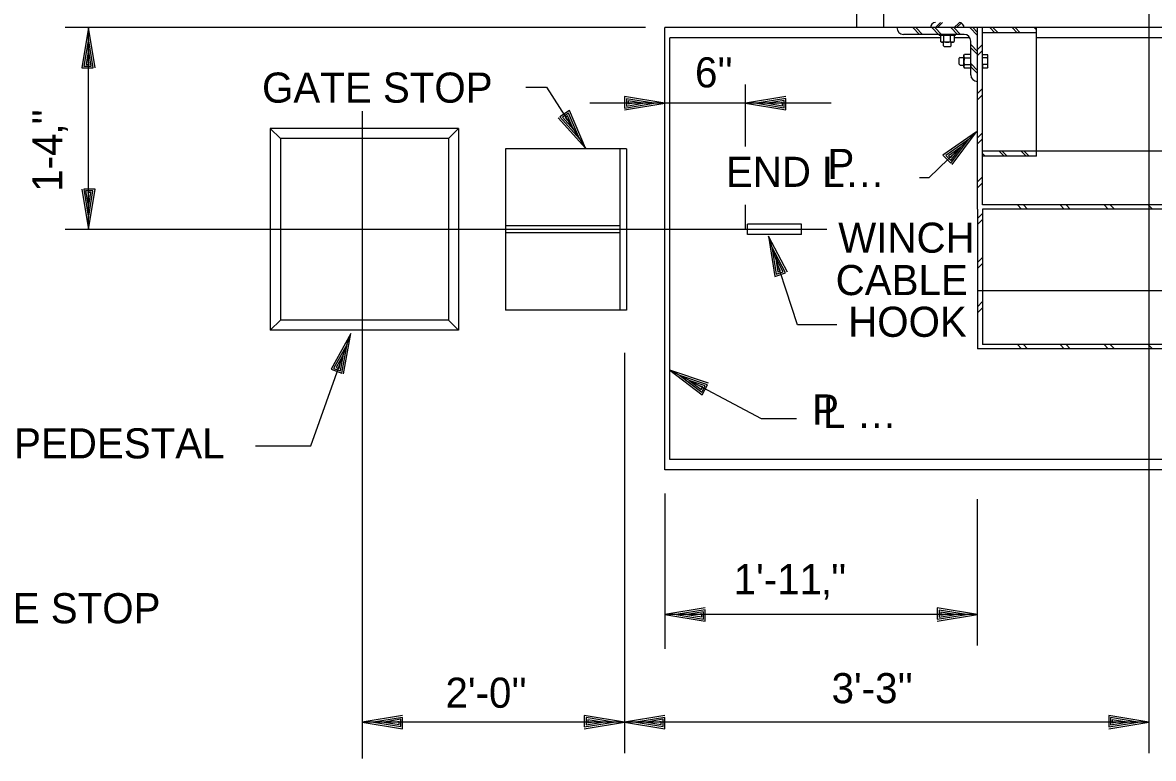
# Model space of a CAD drawing. Extents: x 0 to 53.3, y -2.9 to 37.3.
# Drawn here: x 7.1 to 14.11, y 12.87 to 17.43 of the extents above; entities that cross this region are included whole.
import ezdxf

# ---------------------------------------------------------------- set-up
doc = ezdxf.new("R2010")
doc.units = 0
for name, color, linetype in [('Level 2', 7, 'Continuous'), ('Level 3', 7, 'Continuous'), ('Level 44', 7, 'Continuous'), ('Level 50', 7, 'Continuous')]:
    doc.layers.add(name, color=color, linetype=linetype)

msp = doc.modelspace()

# ---------------------------------------------------------------- linework, layer by layer
at = {"layer": 'Level 2'}
for p, q in [((12.2655, 17.5489), (12.2655, 17.4006)), ((12.4322, 17.5489), (12.4322, 17.4006)), ((47.1285, 17.4006), (11.078, 17.4006)), ((11.078, 14.661), (11.078, 17.4006)), ((13.0155, 16.2756), (13.0155, 17.4006)), ((13.0468, 16.3016), (13.0468, 17.4006)), ((13.3801, 17.3693), (13.3801, 17.4006)), ((13.3801, 16.6037), (13.3801, 17.4006)), ((12.7862, 17.3381), (11.1093, 17.3381)), ((11.1093, 14.7235), (11.1093, 17.3381)), ((12.9322, 17.3589), (12.5572, 17.3589)), ((12.7787, 17.3589), (12.7787, 17.3514)), ((12.8774, 17.3514), (12.7787, 17.3514)), ((12.7862, 17.3514), (12.7862, 17.314)), ((12.7918, 17.3107), (12.7862, 17.314)), ((12.8643, 17.3107), (12.7918, 17.3107)), ((12.8038, 17.2873), (12.8038, 17.3107)), ((12.807, 17.3139), (12.807, 17.3514)), ((12.849, 17.3139), (12.849, 17.3514)), ((12.8523, 17.2873), (12.8523, 17.3107)), ((12.8643, 17.3107), (12.8699, 17.314)), ((12.8699, 17.3514), (12.8699, 17.314)), ((12.9683, 17.3381), (12.8699, 17.3381)), ((12.8774, 17.3589), (12.8774, 17.3514)), ((12.9738, 17.1089), (12.9738, 17.3173)), ((13.3801, 17.3693), (13.0468, 17.3693)), ((47.1285, 17.3381), (13.3801, 17.3381)), ((12.8038, 17.2873), (12.8098, 17.2812)), ((12.8462, 17.2812), (12.8098, 17.2812)), ((12.8523, 17.2873), (12.8462, 17.2812)), ((12.9074, 17.2165), (12.9013, 17.2105)), ((12.9013, 17.1741), (12.9013, 17.2105)), ((12.9074, 17.168), (12.9013, 17.1741)), ((12.9074, 17.2165), (12.9308, 17.2165)), ((12.9308, 17.2285), (12.9341, 17.2341)), ((12.9308, 17.156), (12.9308, 17.2285)), ((12.934, 17.2132), (12.9738, 17.2132)), ((12.934, 17.1713), (12.9738, 17.1713)), ((12.9738, 17.2341), (12.9341, 17.2341)), ((12.9738, 17.1504), (12.9738, 17.2341)), ((12.9738, 17.1716), (12.9738, 17.1504)), ((13.0442, 17.2168), (13.0457, 17.2168)), ((13.0442, 17.1683), (13.0457, 17.1683)), ((13.0457, 17.1506), (13.0457, 17.2344)), ((13.0457, 17.2344), (13.0764, 17.2344)), ((13.0765, 17.2135), (13.0457, 17.2135)), ((13.0457, 17.1718), (13.0457, 17.1506)), ((13.0765, 17.1715), (13.0457, 17.1715)), ((13.0797, 17.2288), (13.0764, 17.2344)), ((13.0797, 17.1563), (13.0797, 17.2288)), ((12.9074, 17.168), (12.9308, 17.168)), ((12.9308, 17.156), (12.9341, 17.1504)), ((12.9738, 17.1504), (12.9341, 17.1504)), ((13.0457, 17.1506), (13.0764, 17.1506)), ((13.0797, 17.1563), (13.0764, 17.1506)), ((9.7993, 16.7756), (8.6326, 16.7756)), ((9.7368, 16.7131), (8.6951, 16.7131)), ((10.841, 16.6506), (10.091, 16.6506)), ((13.3801, 16.635), (13.0468, 16.635)), ((15.1874, 16.635), (13.3801, 16.635)), ((13.3801, 16.6037), (13.0468, 16.6037)), ((47.1285, 16.3016), (13.0468, 16.3016)), ((47.1285, 16.2756), (13.0468, 16.2756)), ((12.0815, 16.1506), (7.3607, 16.1506)), ((10.7993, 16.1714), (10.091, 16.1714)), ((10.7993, 16.1298), (10.091, 16.1298)), ((11.591, 16.1193), (11.591, 16.1818)), ((11.9243, 16.1818), (11.591, 16.1818)), ((11.9243, 16.1193), (11.591, 16.1193)), ((11.9243, 16.1193), (11.9243, 16.1818)), ((47.1285, 15.7698), (13.0155, 15.7698)), ((10.841, 15.6506), (10.091, 15.6506)), ((9.7368, 15.5881), (8.6951, 15.5881)), ((9.7993, 15.5256), (8.6326, 15.5256)), ((47.1285, 15.4364), (13.0468, 15.4364)), ((47.1285, 15.4104), (13.0155, 15.4104)), ((47.1285, 14.7235), (11.1093, 14.7235)), ((47.1285, 14.661), (11.078, 14.661)), ((13.0155, 13.572), (13.0155, 14.4783))]:
    msp.add_line(p, q, dxfattribs=at)
for centre, radius, start, end in [((12.5572, 17.4006), 0.0417, 180, 270), ((12.7551, 17.4006), 0.0313, 90, 180), ((12.9009, 17.4006), 0.0313, 0, 90), ((12.7968, 17.3288), 0.0182, 239.71241, 304.51098), ((12.8283, 17.3834), 0.0727, 253.01837, 286.49659), ((12.8593, 17.3288), 0.0182, 235.48902, 300.28759), ((12.9322, 17.3172), 0.0417, 0, 90), ((12.949, 17.2235), 0.0182, 149.71241, 214.51098), ((12.949, 17.161), 0.0182, 145.48902, 210.28759), ((13.0036, 17.192), 0.0727, 163.01837, 196.49659), ((13.0615, 17.2237), 0.0182, 325.48902, 30.28759), ((13.007, 17.1922), 0.0727, 343.50341, 16.98163), ((13.0615, 17.1612), 0.0182, 329.71241, 34.51098), ((13.0155, 17.1089), 0.0417, 180, 270)]:
    msp.add_arc(centre, radius, start, end, dxfattribs=at)
at = {"layer": 'Level 3'}
for p, q in [((9.203, 16.8825), (9.203, 12.8719)), ((8.6326, 16.7756), (8.6326, 15.5256)), ((9.7993, 16.7756), (9.7993, 15.5256)), ((13.0096, 16.7546), (13.0096, 16.7546)), ((8.6951, 16.7131), (8.6951, 15.5881)), ((9.7368, 16.7131), (9.7368, 15.5881)), ((10.5483, 16.7125), (10.5483, 16.7125)), ((12.9597, 16.7065), (12.9597, 16.7065)), ((10.091, 16.6506), (10.091, 15.6506)), ((10.5856, 16.6541), (10.5856, 16.6541)), ((10.7993, 16.6506), (10.7993, 15.6506)), ((10.841, 16.6506), (10.841, 15.6506)), ((11.7201, 16.1088), (11.7201, 16.1088)), ((11.7418, 16.0429), (11.7418, 16.0429)), ((9.1314, 15.5044), (9.1314, 15.5044)), ((9.1082, 15.4391), (9.1082, 15.4391)), ((11.1093, 15.2783), (11.1093, 15.2783)), ((11.1704, 15.2457), (11.1704, 15.2457))]:
    msp.add_line(p, q, dxfattribs=at)
for points in [[(12.6556, 17.3589), (12.614, 17.4006)], [(12.6745, 17.3589), (12.6328, 17.4006)], [(12.7735, 17.3589), (12.7318, 17.4006)], [(12.7923, 17.3589), (12.7507, 17.4006)], [(12.755, 17.4011), (12.7862, 17.4324)], [(12.7671, 17.4006), (12.7984, 17.4318)], [(12.8913, 17.3589), (12.8497, 17.4006)], [(12.9102, 17.3589), (12.8685, 17.4006)], [(12.8717, 17.4006), (12.9025, 17.4313)], [(12.885, 17.4006), (12.9135, 17.4292)], [(13.0155, 17.3526), (12.9675, 17.4006)], [(13.0155, 17.3715), (12.9864, 17.4006)], [(13.0155, 17.2536), (12.9738, 17.2953)], [(13.0155, 17.2348), (12.9738, 17.2764)], [(13.0155, 17.1358), (12.9738, 17.1774)], [(13.0155, 17.1169), (12.9738, 17.1585)], [(10.2156, 17.0308), (10.3454, 17.0308), (10.5856, 16.6541)], [(10.4167, 16.8421), (10.5856, 16.6541), (10.4864, 16.8865), (10.4268, 16.8485), (10.5483, 16.7125), (10.4809, 16.8703), (10.4427, 16.846), (10.5125, 16.7687), (10.4754, 16.8542), (10.4597, 16.8441), (10.4752, 16.8272)], [(12.6557, 16.4714), (12.7164, 16.4714), (13.0096, 16.7546)], [(12.859, 16.5517), (13.0096, 16.7546), (12.8015, 16.6111), (12.8506, 16.5603), (12.9597, 16.7065), (12.8185, 16.609), (12.85, 16.5764), (12.9118, 16.6602), (12.8354, 16.6068), (12.8484, 16.5934), (12.8619, 16.612)], [(12.143, 15.5588), (11.9008, 15.5588), (11.7201, 16.1088)], [(11.8372, 15.8848), (11.7201, 16.1088), (11.7587, 15.859), (11.8258, 15.8811), (11.7418, 16.0429), (11.768, 15.8733), (11.8111, 15.8874), (11.7626, 15.9796), (11.7774, 15.8876), (11.7951, 15.8934), (11.7842, 15.9137)], [(8.5406, 14.8094), (8.8847, 14.8094), (9.1314, 15.5044)], [(9.0869, 15.2556), (9.1314, 15.5044), (9.0091, 15.2833), (9.0756, 15.2596), (9.1082, 15.4391), (9.0252, 15.2889), (9.0679, 15.2737), (9.0859, 15.3763), (9.0413, 15.2945), (9.0589, 15.2882), (9.0627, 15.3109)], [(11.8935, 14.9757), (11.6773, 14.9757), (11.1093, 15.2783)], [(11.3488, 15.1975), (11.1093, 15.2783), (11.3099, 15.1246), (11.3431, 15.1869), (11.1704, 15.2457), (11.3068, 15.1414), (11.3281, 15.1814), (11.2293, 15.2143), (11.3036, 15.1581), (11.3124, 15.1746), (11.2905, 15.1817)]]:
    msp.add_lwpolyline(points, dxfattribs=at)
at = {"layer": 'Level 44'}
for p, q in [((13.1237, 17.3693), (13.0925, 17.4006)), ((13.1426, 17.3693), (13.1113, 17.4006)), ((13.2604, 17.3693), (13.2292, 17.4006)), ((13.2793, 17.3693), (13.248, 17.4006)), ((13.3801, 17.3864), (13.3659, 17.4006)), ((13.0155, 17.2649), (13.0468, 17.2961)), ((13.0155, 17.2272), (13.0468, 17.2584)), ((11.578, 16.6636), (11.578, 17.048)), ((13.0155, 16.9915), (13.0468, 17.0227)), ((13.0155, 16.9538), (13.0468, 16.985)), ((11.078, 16.9317), (10.6135, 16.9317)), ((11.578, 16.9317), (11.078, 16.9317)), ((12.1094, 16.9317), (11.578, 16.9317)), ((13.0155, 16.7181), (13.0468, 16.7493)), ((13.0155, 16.6803), (13.0468, 16.7116)), ((13.0627, 16.6037), (13.0468, 16.6197)), ((13.1806, 16.6037), (13.1493, 16.635)), ((13.1994, 16.6037), (13.1682, 16.635)), ((13.3173, 16.6037), (13.286, 16.635)), ((13.3361, 16.6037), (13.3049, 16.635)), ((13.0155, 16.4446), (13.0468, 16.4759)), ((13.0155, 16.4069), (13.0468, 16.4382)), ((11.578, 16.1555), (11.578, 16.3028)), ((13.2887, 16.2756), (13.2626, 16.3016)), ((13.3261, 16.2756), (13.3001, 16.3016)), ((13.5526, 16.2756), (13.5266, 16.3016)), ((13.5903, 16.2756), (13.5643, 16.3016)), ((13.826, 16.2756), (13.8, 16.3016)), ((13.8637, 16.2756), (13.8377, 16.3016)), ((14.0994, 16.2756), (14.0734, 16.3016)), ((13.0155, 16.2181), (13.0468, 16.2494)), ((13.0155, 16.1804), (13.0468, 16.2117)), ((13.0155, 15.9447), (13.0468, 15.976)), ((13.0155, 15.907), (13.0468, 15.9382)), ((13.0155, 15.6713), (13.0468, 15.7025)), ((13.0155, 15.6336), (13.0468, 15.6648)), ((13.2887, 15.4104), (13.2626, 15.4364)), ((13.3261, 15.4104), (13.3001, 15.4364)), ((13.5526, 15.4104), (13.5266, 15.4364)), ((13.5903, 15.4104), (13.5643, 15.4364)), ((13.826, 15.4104), (13.8, 15.4364)), ((13.8637, 15.4104), (13.8377, 15.4364)), ((14.0994, 15.4104), (14.0734, 15.4364))]:
    msp.add_line(p, q, dxfattribs=at)
at = {"layer": 'Level 50'}
for p, q in [((14.078, 17.5383), (14.078, 12.904)), ((10.9573, 17.4006), (7.3607, 17.4006)), ((7.5058, 16.1506), (7.5058, 17.4006)), ((7.5058, 17.4006), (7.5058, 17.4006)), ((7.5058, 17.3313), (7.5058, 17.3313)), ((11.0087, 16.9317), (11.0087, 16.9317)), ((11.078, 16.9317), (11.078, 16.9317)), ((11.578, 16.9317), (11.578, 16.9317)), ((11.6473, 16.9317), (11.6473, 16.9317)), ((8.6951, 16.7131), (8.6326, 16.7756)), ((9.7368, 16.7131), (9.7993, 16.7756)), ((13.0155, 16.2756), (13.0155, 15.4104)), ((13.0468, 16.2756), (13.0468, 15.4364)), ((7.5058, 16.2199), (7.5058, 16.2199)), ((7.5058, 16.1506), (7.5058, 16.1506)), ((8.6326, 15.5256), (8.6951, 15.5881)), ((9.7368, 15.5881), (9.7993, 15.5256)), ((10.828, 15.3846), (10.828, 12.904)), ((11.078, 14.5145), (11.078, 13.5518)), ((13.0155, 13.7635), (11.078, 13.7635)), ((11.078, 13.7635), (11.078, 13.7635)), ((11.1473, 13.7635), (11.1473, 13.7635)), ((12.9462, 13.7635), (12.9462, 13.7635)), ((13.0155, 13.7635), (13.0155, 13.7635)), ((10.828, 13.0968), (9.203, 13.0968)), ((9.203, 13.0968), (9.203, 13.0968)), ((9.2723, 13.0968), (9.2723, 13.0968)), ((10.7587, 13.0968), (10.7587, 13.0968)), ((14.078, 13.0968), (10.828, 13.0968)), ((10.828, 13.0968), (10.828, 13.0968)), ((10.828, 13.0968), (10.828, 13.0968)), ((10.8973, 13.0968), (10.8973, 13.0968)), ((14.0087, 13.0968), (14.0087, 13.0968)), ((14.078, 13.0968), (14.078, 13.0968))]:
    msp.add_line(p, q, dxfattribs=at)
for points in [[(7.5472, 17.1513), (7.5058, 17.4006), (7.4645, 17.1513), (7.5352, 17.1513), (7.5058, 17.3313), (7.4778, 17.1619), (7.5232, 17.1619), (7.5058, 17.2646), (7.4912, 17.1726), (7.5098, 17.1726), (7.5058, 17.1953)], [(10.8287, 16.8904), (11.078, 16.9317), (10.8287, 16.9731), (10.8287, 16.9024), (11.0087, 16.9317), (10.8393, 16.9597), (10.8393, 16.9144), (10.942, 16.9317), (10.85, 16.9464), (10.85, 16.9277), (10.8727, 16.9317)], [(11.8273, 16.9731), (11.578, 16.9317), (11.8273, 16.8904), (11.8273, 16.9611), (11.6473, 16.9317), (11.8167, 16.9037), (11.8167, 16.9491), (11.714, 16.9317), (11.806, 16.9171), (11.806, 16.9357), (11.7833, 16.9317)], [(7.4645, 16.3999), (7.5058, 16.1506), (7.5472, 16.3999), (7.4765, 16.3999), (7.5058, 16.2199), (7.5338, 16.3893), (7.4885, 16.3893), (7.5058, 16.2866), (7.5205, 16.3786), (7.5018, 16.3786), (7.5058, 16.3559)], [(11.3273, 13.8048), (11.078, 13.7635), (11.3273, 13.7222), (11.3273, 13.7928), (11.1473, 13.7635), (11.3167, 13.7355), (11.3167, 13.7808), (11.214, 13.7635), (11.306, 13.7488), (11.306, 13.7675), (11.2833, 13.7635)], [(12.7662, 13.7222), (13.0155, 13.7635), (12.7662, 13.8048), (12.7662, 13.7342), (12.9462, 13.7635), (12.7768, 13.7915), (12.7768, 13.7462), (12.8795, 13.7635), (12.7875, 13.7782), (12.7875, 13.7595), (12.8102, 13.7635)], [(9.4523, 13.1382), (9.203, 13.0968), (9.4523, 13.0555), (9.4523, 13.1262), (9.2723, 13.0968), (9.4417, 13.0688), (9.4417, 13.1142), (9.339, 13.0968), (9.431, 13.0822), (9.431, 13.1008), (9.4083, 13.0968)], [(10.5787, 13.0555), (10.828, 13.0968), (10.5787, 13.1382), (10.5787, 13.0675), (10.7587, 13.0968), (10.5893, 13.1248), (10.5893, 13.0795), (10.692, 13.0968), (10.6, 13.1115), (10.6, 13.0928), (10.6227, 13.0968)], [(11.0773, 13.1382), (10.828, 13.0968), (11.0773, 13.0555), (11.0773, 13.1262), (10.8973, 13.0968), (11.0667, 13.0688), (11.0667, 13.1142), (10.964, 13.0968), (11.056, 13.0822), (11.056, 13.1008), (11.0333, 13.0968)], [(13.8287, 13.0555), (14.078, 13.0968), (13.8287, 13.1382), (13.8287, 13.0675), (14.0087, 13.0968), (13.8393, 13.1248), (13.8393, 13.0795), (13.942, 13.0968), (13.85, 13.1115), (13.85, 13.0928), (13.8727, 13.0968)]]:
    msp.add_lwpolyline(points, dxfattribs=at)

# ---------------------------------------------------------------- texts
at = {"layer": 'Level 44'}
for s, p in [("6''", (11.2646, 17.0303)), ('P', (12.0854, 16.4627)), ('END L…', (11.4562, 16.4139)), ('WINCH', (12.1521, 16.0057)), ('CABLE', (12.1363, 15.743)), ('HOOK', (12.2137, 15.4845))]:
    msp.add_text(s, height=0.1867, dxfattribs=at).set_placement(p)
at = {"layer": 'Level 50'}
for s, height, p in [('GATE STOP', 0.1867, (8.5816, 16.9357)), ('P', 0.1867, (11.9906, 14.9406)), ('L …', 0.1867, (12.0583, 14.9186)), ('WINCH PEDESTAL', 0.186698, (6.1298, 14.731)), ("1'-11‚''", 0.1867, (11.5044, 13.8895)), ('FOR WINCH PEDESTAL AND GATE STOP', 0.186698, (3.0415, 13.7092)), ("3'-3''", 0.1867, (12.1112, 13.2139)), ("2'-0''", 0.1867, (9.7184, 13.1857))]:
    msp.add_text(s, height=height, dxfattribs=at).set_placement(p)
msp.add_text("1-4‚''", height=0.1867, rotation=90, dxfattribs=at).set_placement((7.3439, 16.3837))

doc.saveas('drawing.dxf')
